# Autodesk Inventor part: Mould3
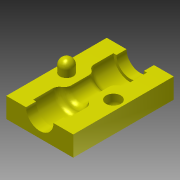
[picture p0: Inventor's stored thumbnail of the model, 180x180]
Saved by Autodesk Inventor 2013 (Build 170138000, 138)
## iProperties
Created: 2013-06
Part Number: Mould3
Material: Generic
Document SubType Name: Modeling
Designer: frankenteddy
Density: 1 g/cm^3
Author: frankenteddy
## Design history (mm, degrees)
sketch "Sketch1"
  geometry: L1 (-10, 12)-(10, 12); L2 (10, 12)-(10, -12); L3 (10, -12)-(-10, -12); L4 (-10, -12)-(-10, 12); L5 (-10, 12)-(-10, 15); L6 (-10, 15)-(10, 15); L7 (10, 15)-(10, 12); 3 further points
  constraints: 14 end point, 3 parallel, 2 midpoint, 2 perpendicular, 1 collinear, 1 horizontal, 1 horizontal alignment, 1 vertical alignment
  dimensions: "d0" = 24 distance of L1.end L2.end; "d2" = 20 distance of L1.start L1.end; "d65" = 3 distance of L1.start L5.end
extrude "Extrusion1" new body sketch "Sketch1" distance "d3" = 6; taper "d4" = 0 deg
workplane "Work Plane1"
sketch "Sketch2"
  geometry: L1 (-10, -12)-(10, -12) reference; L2 (5, 12)-(5, 6.138); L3 (0, 12)-(5, 12); L4 (3, 2.674)-(3, 0); L5 (3, 0)-(0, 0); L6 (0, 0)-(0, 12); A1 r 2 centre (5, 2.674) between (4, 4.406) and (3, 2.674); A2 r 2 centre (3, 6.138) between (4, 4.406) and (5, 6.138); 3 further points
  constraints: 10 end point, 4 point on circle, 3 perpendicular, 3 tangent, 2 centre point, 2 vertical alignment, 1 horizontal, 1 parallel
  dimensions: "d15" = 2 radius of A1; "d18" = 2 radius of A2; "d55" = 5 distance of L3.start L2.start; "d56" = 3 distance between parallel lines of L6 L4; "d59" = 12 distance between parallel lines of L5 L3
revolve "Revolution1" sketch "Sketch2" stored, may be unused: angle "d20" = 90 deg
mirror "Mirror1"
workplane "Work Plane2"
sketch "Sketch3"
  geometry: L1 (-17.279, 0)-(16.833, 0) reference; L2 (0, 16.632)-(0, -16.118) reference; L3 (17.279, 0)-(-16.833, 0); L4 (-1, 9)-(-3, 9); L5 (-3, 9)-(-3, 8); L6 (-3, 8)-(-1, 8); L7 (-1, 8)-(-1, 9); C1 r 2 at (-7, 0); C2 r 2.2 at (7, 0); 1 further point
  constraints: 14 end point, 3 horizontal, 2 centre point, 2 parallel, 2 perpendicular, 2 symmetric about line, 1 vertical
  dimensions: "d24" = 4 diameter of C1; "d26" = 0 vertical distance of point (0, 0) C1.centre; "d27" = 7 distance of point (0, 0) C1.centre; "d36" = 4.4 diameter of C2; "d37" = 7 distance from line of L2 C2.centre; "d38" = 0 distance from line of L1 C2.centre; "d47" = 2 distance of L6.end L5.end; "d48" = 1 distance of L5.end L4.end; "d49" = 1 distance between parallel lines of L2 L7; "d50" = 8 distance between parallel lines of L1 L6
extrude "Extrusion6" join sketch "Sketch3" distance "d60" = 4; taper "d61" = 0 deg
extrude "Extrusion7" cut sketch "Sketch3" distance "d62" = 4; taper "d63" = 0 deg
fillet "Fillet3" dims "d64" = 2
extrude "Extrusion8" join sketch "Sketch1" distance "d66" = 6; taper "d67" = 0 deg
workplane "Work Plane3"
sketch "Sketch5"
  geometry: L1 (0, 15)-(4.1, 15); L2 (4.1, 15)-(4.1, 12); L3 (4.1, 12)-(0, 12); L4 (0, 12)-(0, 15); 1 further point
  constraints: 8 end point, 2 parallel, 1 horizontal, 1 perpendicular
  dimensions: "d71" = 4.1 distance of L2.end L3.end; "d72" = 3 distance of L1.end L2.end; "d73" = 12 distance from line of L3 point (0, 0)
revolve "Revolution4" sketch "Sketch5" stored, may be unused: angle "d74" = 90 deg
mirror "Mirror3"
body "Solid1"
other parameters: "d5" = 6, "d23" = 6, "d70" = 6
